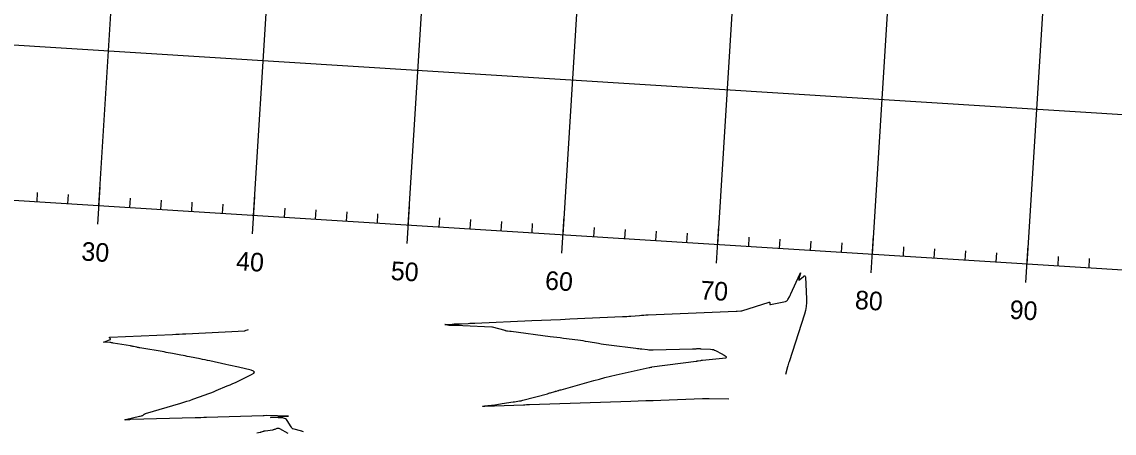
# Model space of a CAD drawing. Extents: x 658976 to 668721, y 639543 to 647196.
# Drawn here: x 662494.8 to 662847.1, y 641722.9 to 641855.6 of the extents above; entities that cross this region are included whole.
import ezdxf

# ---------------------------------------------------------------- set-up
doc = ezdxf.new("R2010")
doc.units = 0
for name, color, linetype in [('Ex_Minor Contours', 7, 'Continuous'), ('R_Axis', 7, 'Continuous'), ('R_Axis Annot', 7, 'Continuous'), ('R_Grid', 7, 'Continuous')]:
    doc.layers.add(name, color=color, linetype=linetype)

msp = doc.modelspace()

# ---------------------------------------------------------------- linework, layer by layer
at = {"layer": 'Ex_Minor Contours'}
for points in [[(662722.87, 641733.85), (662716.46, 641733.95), (662715.94, 641733.96), (662715.43, 641733.95), (662714.92, 641733.95), (662714.41, 641733.93), (662700.9, 641733.43), (662698.47, 641733.34), (662696.05, 641733.25), (662693.63, 641733.17), (662691.2, 641733.08), (662658.52, 641731.99), (662658.04, 641731.97), (662657.56, 641731.96), (662657.08, 641731.94), (662656.6, 641731.92), (662644.1, 641731.5), (662643.54, 641731.49), (662643.35, 641731.51), (662643.53, 641731.56), (662644.09, 641731.64), (662647.37, 641732.05), (662647.97, 641732.13), (662648.57, 641732.21), (662649.18, 641732.3), (662649.78, 641732.38), (662653.29, 641732.92), (662653.33, 641732.93), (662653.37, 641732.93), (662653.41, 641732.94), (662653.45, 641732.95), (662653.68, 641733), (662653.69, 641733.01), (662653.7, 641733.01), (662655.32, 641733.24), (662655.59, 641733.28), (662655.86, 641733.33), (662656.13, 641733.39), (662656.39, 641733.46), (662664.31, 641735.6), (662664.58, 641735.67), (662664.84, 641735.75), (662665.11, 641735.83), (662665.38, 641735.91), (662666.72, 641736.31), (662666.84, 641736.35), (662666.97, 641736.39), (662667.1, 641736.42), (662667.23, 641736.46), (662667.84, 641736.61), (662667.92, 641736.63), (662668, 641736.65), (662668.08, 641736.68), (662668.15, 641736.7), (662668.46, 641736.8), (662668.54, 641736.82), (662668.62, 641736.85), (662668.7, 641736.87), (662668.78, 641736.89), (662679.3, 641739.84), (662681.08, 641740.33), (662682.86, 641740.79), (662684.66, 641741.23), (662686.46, 641741.64), (662697.15, 641744), (662697.21, 641744.02), (662697.27, 641744.03), (662697.33, 641744.04), (662697.39, 641744.06), (662697.67, 641744.13), (662697.71, 641744.14), (662697.74, 641744.15), (662697.77, 641744.16), (662697.8, 641744.16), (662697.93, 641744.19), (662697.96, 641744.2), (662697.99, 641744.21), (662698.03, 641744.21), (662698.06, 641744.22), (662712.34, 641746.1), (662712.51, 641746.12), (662712.67, 641746.15), (662712.84, 641746.18), (662713.01, 641746.2), (662713.67, 641746.32), (662713.84, 641746.35), (662714, 641746.37), (662714.17, 641746.4), (662714.34, 641746.42), (662721.88, 641747.18), (662722.03, 641747.22), (662722.09, 641747.27), (662722.07, 641747.35), (662721.96, 641747.46), (662721.37, 641747.93), (662721.22, 641748.04), (662721.07, 641748.15), (662720.91, 641748.25), (662720.74, 641748.34), (662718.68, 641749.39), (662718.28, 641749.57), (662717.86, 641749.71), (662717.43, 641749.8), (662716.99, 641749.85), (662713.95, 641750.01), (662713.81, 641750.01), (662713.66, 641750.02), (662713.52, 641750.02), (662713.38, 641750.02), (662712.8, 641750.02), (662712.67, 641750.02), (662712.53, 641750.02), (662712.39, 641750.02), (662712.25, 641750.01), (662711.69, 641749.99), (662711.55, 641749.99), (662711.41, 641749.98), (662711.27, 641749.98), (662711.14, 641749.98), (662698.47, 641749.64), (662698, 641749.64), (662697.53, 641749.65), (662697.07, 641749.68), (662696.6, 641749.73), (662694.74, 641749.95), (662694.28, 641750.01), (662693.81, 641750.07), (662693.35, 641750.12), (662692.88, 641750.18), (662684.12, 641751.26), (662683.28, 641751.37), (662682.45, 641751.48), (662681.62, 641751.61), (662680.8, 641751.75), (662677.49, 641752.33), (662676.66, 641752.47), (662675.83, 641752.6), (662675, 641752.72), (662674.17, 641752.83), (662669.47, 641753.44), (662668.41, 641753.58), (662667.35, 641753.71), (662666.29, 641753.85), (662665.23, 641753.99), (662652.64, 641755.63), (662652.61, 641755.63), (662652.57, 641755.64), (662652.53, 641755.64), (662652.49, 641755.65), (662652.34, 641755.66), (662652.31, 641755.67), (662652.27, 641755.67), (662652.23, 641755.68), (662652.19, 641755.68), (662651.51, 641755.76), (662651.44, 641755.77), (662651.37, 641755.78), (662651.3, 641755.79), (662651.23, 641755.81), (662650.94, 641755.88), (662650.87, 641755.9), (662650.8, 641755.92), (662650.73, 641755.93), (662650.66, 641755.95), (662646.6, 641757.03), (662646.58, 641757.03), (662646.57, 641757.04), (662646.55, 641757.04), (662646.53, 641757.04), (662646.46, 641757.04), (662646.45, 641757.04), (662646.43, 641757.04), (662646.41, 641757.04), (662646.4, 641757.04), (662637.02, 641757.54), (662636.57, 641757.56), (662636.11, 641757.58), (662635.66, 641757.59), (662635.2, 641757.6), (662632.82, 641757.64), (662632.64, 641757.65), (662632.47, 641757.67), (662632.29, 641757.69), (662632.12, 641757.72), (662631.42, 641757.86), (662631.3, 641757.9), (662631.25, 641757.92), (662631.3, 641757.94), (662631.43, 641757.95), (662633.61, 641758.05), (662633.8, 641758.06), (662633.98, 641758.07), (662634.17, 641758.08), (662634.36, 641758.09), (662635.1, 641758.12), (662635.29, 641758.13), (662635.47, 641758.14), (662635.66, 641758.15), (662635.85, 641758.15), (662638.75, 641758.28), (662639.3, 641758.3), (662639.85, 641758.32), (662640.4, 641758.35), (662640.94, 641758.37), (662659.33, 641759.17), (662662.39, 641759.3), (662665.45, 641759.43), (662668.5, 641759.57), (662671.56, 641759.7), (662688.52, 641760.46), (662689.21, 641760.49), (662689.9, 641760.53), (662690.59, 641760.58), (662691.28, 641760.63), (662694.03, 641760.85), (662694.72, 641760.9), (662695.41, 641760.95), (662696.1, 641760.99), (662696.79, 641761.02), (662725.17, 641762.19), (662725.28, 641762.19), (662725.38, 641762.2), (662725.49, 641762.2), (662725.59, 641762.21), (662726.74, 641762.29), (662726.82, 641762.3), (662726.89, 641762.31), (662726.97, 641762.33), (662727.05, 641762.35), (662735.85, 641765.11), (662735.94, 641765.12), (662736.01, 641765.1), (662736.05, 641765.04), (662736.07, 641764.95), (662736.08, 641764.5), (662736.1, 641764.41), (662736.14, 641764.35), (662736.21, 641764.32), (662736.3, 641764.33), (662741.12, 641765.37), (662741.36, 641765.44), (662741.57, 641765.57), (662741.75, 641765.73), (662741.89, 641765.94), (662742.39, 641766.86), (662742.52, 641767.09), (662742.64, 641767.32), (662742.75, 641767.56), (662742.86, 641767.79), (662745.76, 641774.19), (662745.89, 641774.46), (662745.95, 641774.54), (662745.95, 641774.44), (662745.87, 641774.15), (662745.43, 641772.63), (662745.38, 641772.34), (662745.42, 641772.2), (662745.56, 641772.23), (662745.8, 641772.41), (662746.95, 641773.44), (662747.2, 641773.62), (662747.39, 641773.63), (662747.51, 641773.49), (662747.56, 641773.18), (662747.94, 641766.25), (662747.95, 641764.97), (662747.84, 641763.71), (662747.62, 641762.46), (662747.28, 641761.23), (662742.27, 641745.83), (662742.15, 641745.43), (662742.02, 641745.03), (662741.9, 641744.63), (662741.79, 641744.23), (662741.1, 641741.83)], [(662585.69, 641723.32), (662585.37, 641723.4), (662585.32, 641723.42), (662585.27, 641723.43), (662585.21, 641723.44), (662585.16, 641723.46), (662582.2, 641724.23), (662582.14, 641724.25), (662582.08, 641724.29), (662582.03, 641724.33), (662581.99, 641724.38), (662581.85, 641724.62), (662581.82, 641724.68), (662581.78, 641724.74), (662581.74, 641724.79), (662581.71, 641724.85), (662580.42, 641726.91), (662580.17, 641727.23), (662579.87, 641727.47), (662579.51, 641727.62), (662579.11, 641727.69), (662575.76, 641727.87), (662575.23, 641727.91), (662575.06, 641727.95), (662575.23, 641727.99), (662575.76, 641728.04), (662580.81, 641728.33), (662580.81, 641728.33), (662580.82, 641728.33), (662580.82, 641728.33), (662580.83, 641728.34), (662580.84, 641728.34), (662580.84, 641728.35), (662580.85, 641728.35), (662580.84, 641728.35), (662580.84, 641728.35), (662580.77, 641728.38), (662580.75, 641728.38), (662580.74, 641728.39), (662580.72, 641728.39), (662580.71, 641728.39), (662573.88, 641728.51), (662573.86, 641728.51), (662573.84, 641728.51), (662573.83, 641728.51), (662573.81, 641728.51), (662572.96, 641728.48), (662572.89, 641728.48), (662572.82, 641728.47), (662572.75, 641728.47), (662572.67, 641728.47), (662554.39, 641727.91), (662553.46, 641727.88), (662552.53, 641727.85), (662551.61, 641727.83), (662550.68, 641727.8), (662529.91, 641727.22), (662529.73, 641727.22), (662529.54, 641727.21), (662529.35, 641727.21), (662529.17, 641727.2), (662528.1, 641727.17), (662528.08, 641727.17), (662528.07, 641727.17), (662528.07, 641727.18), (662528.08, 641727.2), (662528.14, 641727.27), (662528.16, 641727.29), (662528.18, 641727.3), (662528.2, 641727.31), (662528.22, 641727.31), (662532.73, 641728.31), (662532.79, 641728.33), (662532.86, 641728.34), (662532.92, 641728.36), (662532.99, 641728.37), (662533.38, 641728.47), (662533.39, 641728.47), (662533.4, 641728.47), (662533.65, 641728.51), (662533.69, 641728.52), (662533.73, 641728.53), (662533.77, 641728.55), (662533.8, 641728.58), (662534.28, 641728.96), (662534.38, 641729.02), (662534.47, 641729.08), (662534.58, 641729.13), (662534.69, 641729.17), (662546.09, 641732.52), (662547.07, 641732.82), (662548.04, 641733.13), (662549.01, 641733.45), (662549.98, 641733.79), (662553.94, 641735.2), (662554.84, 641735.53), (662555.74, 641735.88), (662556.64, 641736.23), (662557.52, 641736.6), (662561.07, 641738.09), (662561.96, 641738.46), (662562.84, 641738.85), (662563.71, 641739.25), (662564.58, 641739.66), (662568.93, 641741.74), (662569.64, 641742.17), (662569.85, 641742.54), (662569.57, 641742.87), (662568.79, 641743.14), (662564.68, 641744.12), (662563.65, 641744.36), (662562.62, 641744.6), (662561.6, 641744.84), (662560.56, 641745.06), (662555.49, 641746.18), (662554.7, 641746.35), (662553.9, 641746.52), (662553.1, 641746.68), (662552.3, 641746.84), (662548.86, 641747.51), (662548.18, 641747.64), (662547.5, 641747.77), (662546.81, 641747.91), (662546.13, 641748.04), (662543.4, 641748.56), (662542.72, 641748.69), (662542.03, 641748.82), (662541.35, 641748.94), (662540.66, 641749.06), (662532.9, 641750.4), (662532.64, 641750.44), (662532.38, 641750.49), (662532.13, 641750.54), (662531.87, 641750.59), (662530.85, 641750.8), (662530.6, 641750.85), (662530.34, 641750.9), (662530.08, 641750.94), (662529.83, 641750.99), (662524.31, 641751.95), (662524.03, 641751.99), (662523.74, 641752.03), (662523.46, 641752.06), (662523.17, 641752.08), (662521.53, 641752.19), (662521.49, 641752.19), (662521.45, 641752.2), (662521.41, 641752.2), (662521.38, 641752.2), (662521.23, 641752.22), (662521.2, 641752.22), (662521.19, 641752.23), (662521.2, 641752.24), (662521.23, 641752.25), (662523.29, 641753.04), (662523.37, 641753.08), (662523.41, 641753.14), (662523.4, 641753.21), (662523.36, 641753.29), (662523.08, 641753.63), (662523.04, 641753.71), (662523.04, 641753.77), (662523.08, 641753.8), (662523.17, 641753.82), (662543.4, 641754.74), (662544.47, 641754.79), (662545.54, 641754.84), (662546.6, 641754.89), (662547.67, 641754.95), (662566.71, 641755.91), (662566.75, 641755.92), (662566.79, 641755.92), (662566.83, 641755.93), (662566.87, 641755.94), (662567.96, 641756.29)], [(662570.6, 641723), (662571.7, 641723.18), (662571.79, 641723.2), (662571.88, 641723.22), (662571.97, 641723.24), (662572.06, 641723.27), (662572.71, 641723.5), (662572.84, 641723.54), (662572.98, 641723.58), (662573.13, 641723.61), (662573.27, 641723.64), (662575.74, 641723.98), (662575.93, 641724.01), (662576.11, 641724.05), (662576.29, 641724.1), (662576.47, 641724.16), (662577.19, 641724.42), (662577.36, 641724.46), (662577.54, 641724.47), (662577.71, 641724.44), (662577.87, 641724.36), (662580.56, 641722.86)]]:
    msp.add_lwpolyline(points, dxfattribs=at)
at = {"layer": 'R_Axis'}
for p, q in [((661621.43, 641852.69), (663118.48, 641758.67)), ((662499.7, 641797.53), (662499.89, 641800.52)), ((662519.28, 641790.29), (662520.04, 641802.26)), ((662509.68, 641796.9), (662509.87, 641799.9)), ((662529.64, 641795.65), (662529.83, 641798.64)), ((662539.62, 641795.02), (662539.81, 641798.02)), ((662549.6, 641794.4), (662549.79, 641797.39)), ((662569.19, 641787.15), (662569.94, 641799.13)), ((662559.58, 641793.77), (662559.77, 641796.76)), ((662579.54, 641792.52), (662579.73, 641795.51)), ((662589.52, 641791.89), (662589.71, 641794.88)), ((662599.5, 641791.26), (662599.69, 641794.26)), ((662609.48, 641790.63), (662609.67, 641793.63)), ((662619.09, 641784.02), (662619.84, 641796)), ((662629.44, 641789.38), (662629.63, 641792.38)), ((662639.42, 641788.75), (662639.61, 641791.75)), ((662649.4, 641788.13), (662649.59, 641791.12)), ((662659.38, 641787.5), (662659.57, 641790.49)), ((662668.99, 641780.89), (662669.74, 641792.86)), ((662679.35, 641786.25), (662679.53, 641789.24)), ((662689.33, 641785.62), (662689.51, 641788.61)), ((662699.31, 641784.99), (662699.49, 641787.99)), ((662709.29, 641784.37), (662709.47, 641787.36)), ((662718.89, 641777.75), (662719.64, 641789.73)), ((662768.79, 641774.62), (662769.54, 641786.59)), ((662729.25, 641783.11), (662729.44, 641786.11)), ((662739.23, 641782.49), (662739.42, 641785.48)), ((662749.21, 641781.86), (662749.4, 641784.85)), ((662759.19, 641781.23), (662759.38, 641784.23)), ((662779.15, 641779.98), (662779.34, 641782.97)), ((662818.69, 641771.48), (662819.45, 641783.46)), ((662789.13, 641779.35), (662789.32, 641782.35)), ((662799.11, 641778.73), (662799.3, 641781.72)), ((662809.09, 641778.1), (662809.28, 641781.09)), ((662829.05, 641776.84), (662829.24, 641779.84)), ((662839.03, 641776.22), (662839.22, 641779.21))]:
    msp.add_line(p, q, dxfattribs=at)
at = {"layer": 'R_Grid'}
for p, q in [((662519.66, 641796.28), (662535.33, 642045.78)), ((662569.56, 641793.14), (662585.23, 642042.65)), ((662619.46, 641790.01), (662635.13, 642039.52)), ((662669.37, 641786.87), (662685.04, 642036.38)), ((662719.27, 641783.74), (662734.94, 642033.25)), ((662769.17, 641780.61), (662784.84, 642030.11)), ((662819.07, 641777.47), (662834.74, 642026.98)), ((661624.56, 641902.59), (663121.61, 641808.57)), ((661621.43, 641852.69), (663118.48, 641758.67))]:
    msp.add_line(p, q, dxfattribs=at)

# ---------------------------------------------------------------- texts
at = {"layer": 'R_Axis Annot'}
for s, p in [('30', (662513.89, 641778.6)), ('40', (662563.79, 641775.47)), ('50', (662613.69, 641772.33)), ('60', (662663.45, 641769.21)), ('70', (662713.5, 641766.07)), ('80', (662763.4, 641762.93)), ('90', (662813.3, 641759.8))]:
    msp.add_text(s, height=6, rotation=356.4063, dxfattribs=at).set_placement(p)

doc.saveas('drawing.dxf')
